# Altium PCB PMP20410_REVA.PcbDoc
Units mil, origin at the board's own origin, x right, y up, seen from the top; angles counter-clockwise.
Board outline 2100 x 1400 mil, 4 copper layers (Top Layer, Signal Layer 1, Signal Layer 2, Bottom Layer), stack 68.2 mil thick; 65 components, 35 nets, 168 pads, 100 vias.
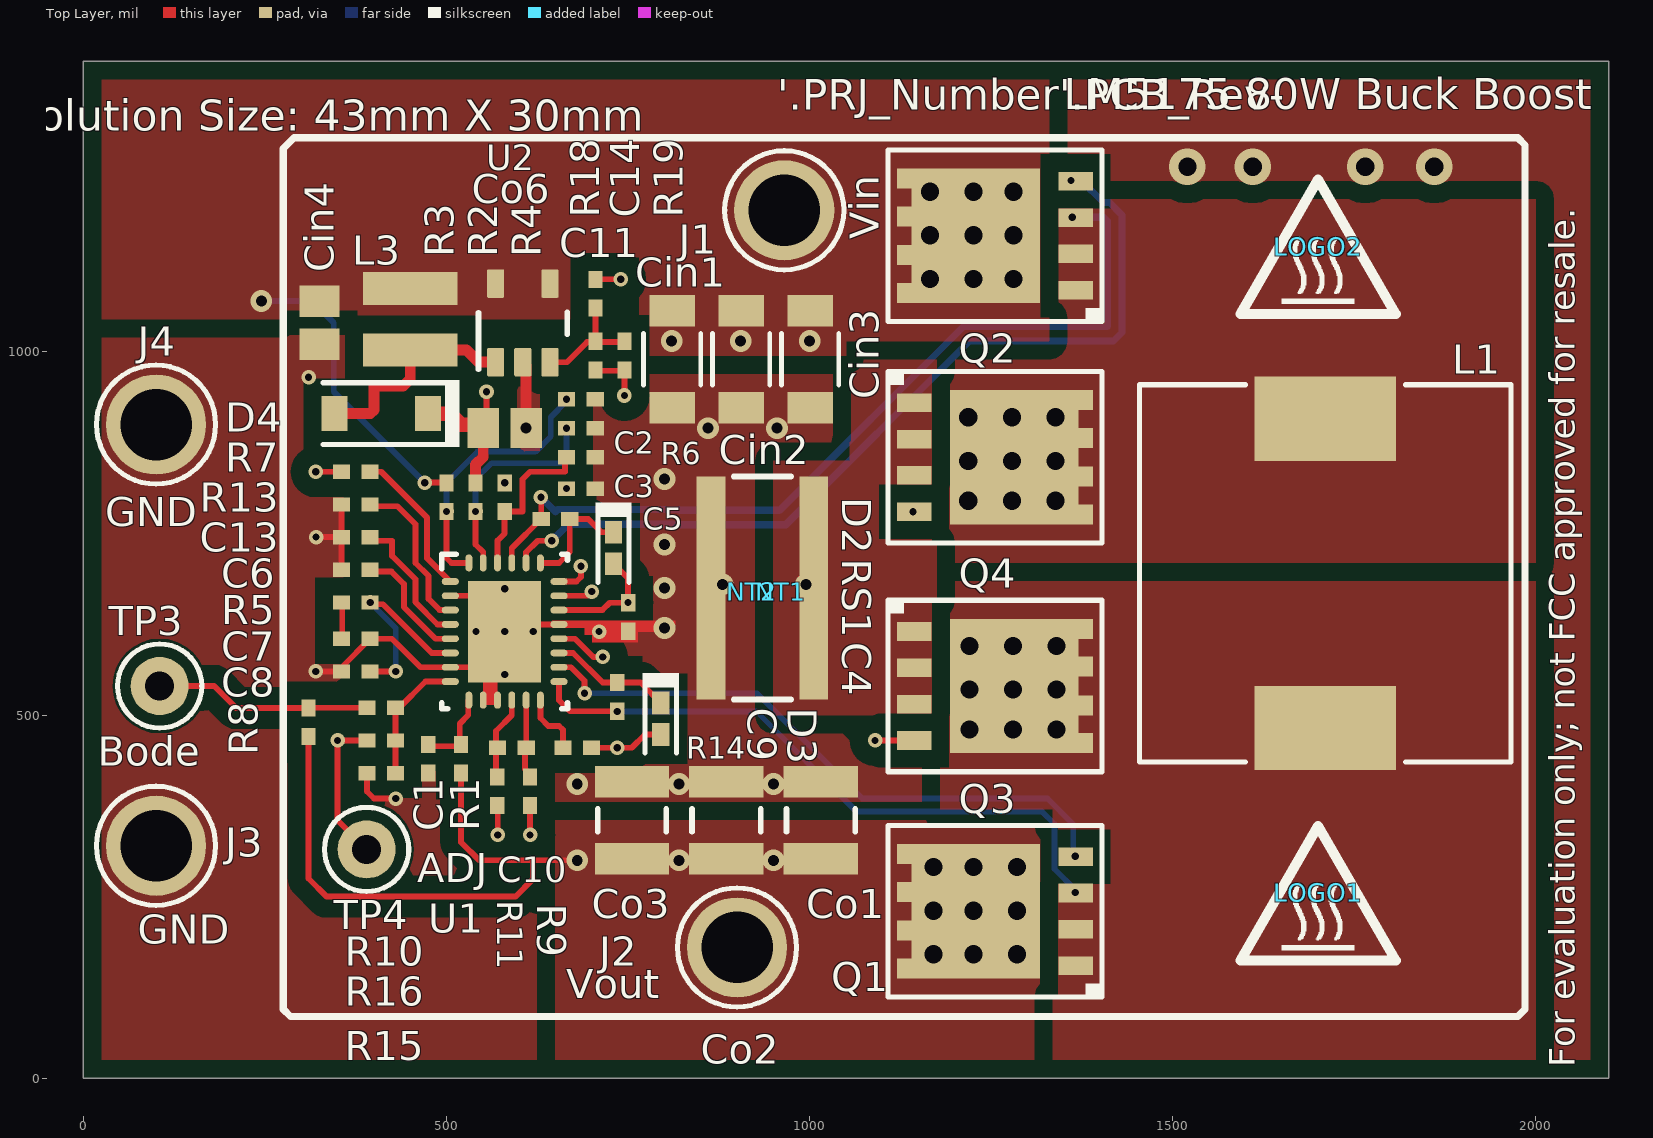
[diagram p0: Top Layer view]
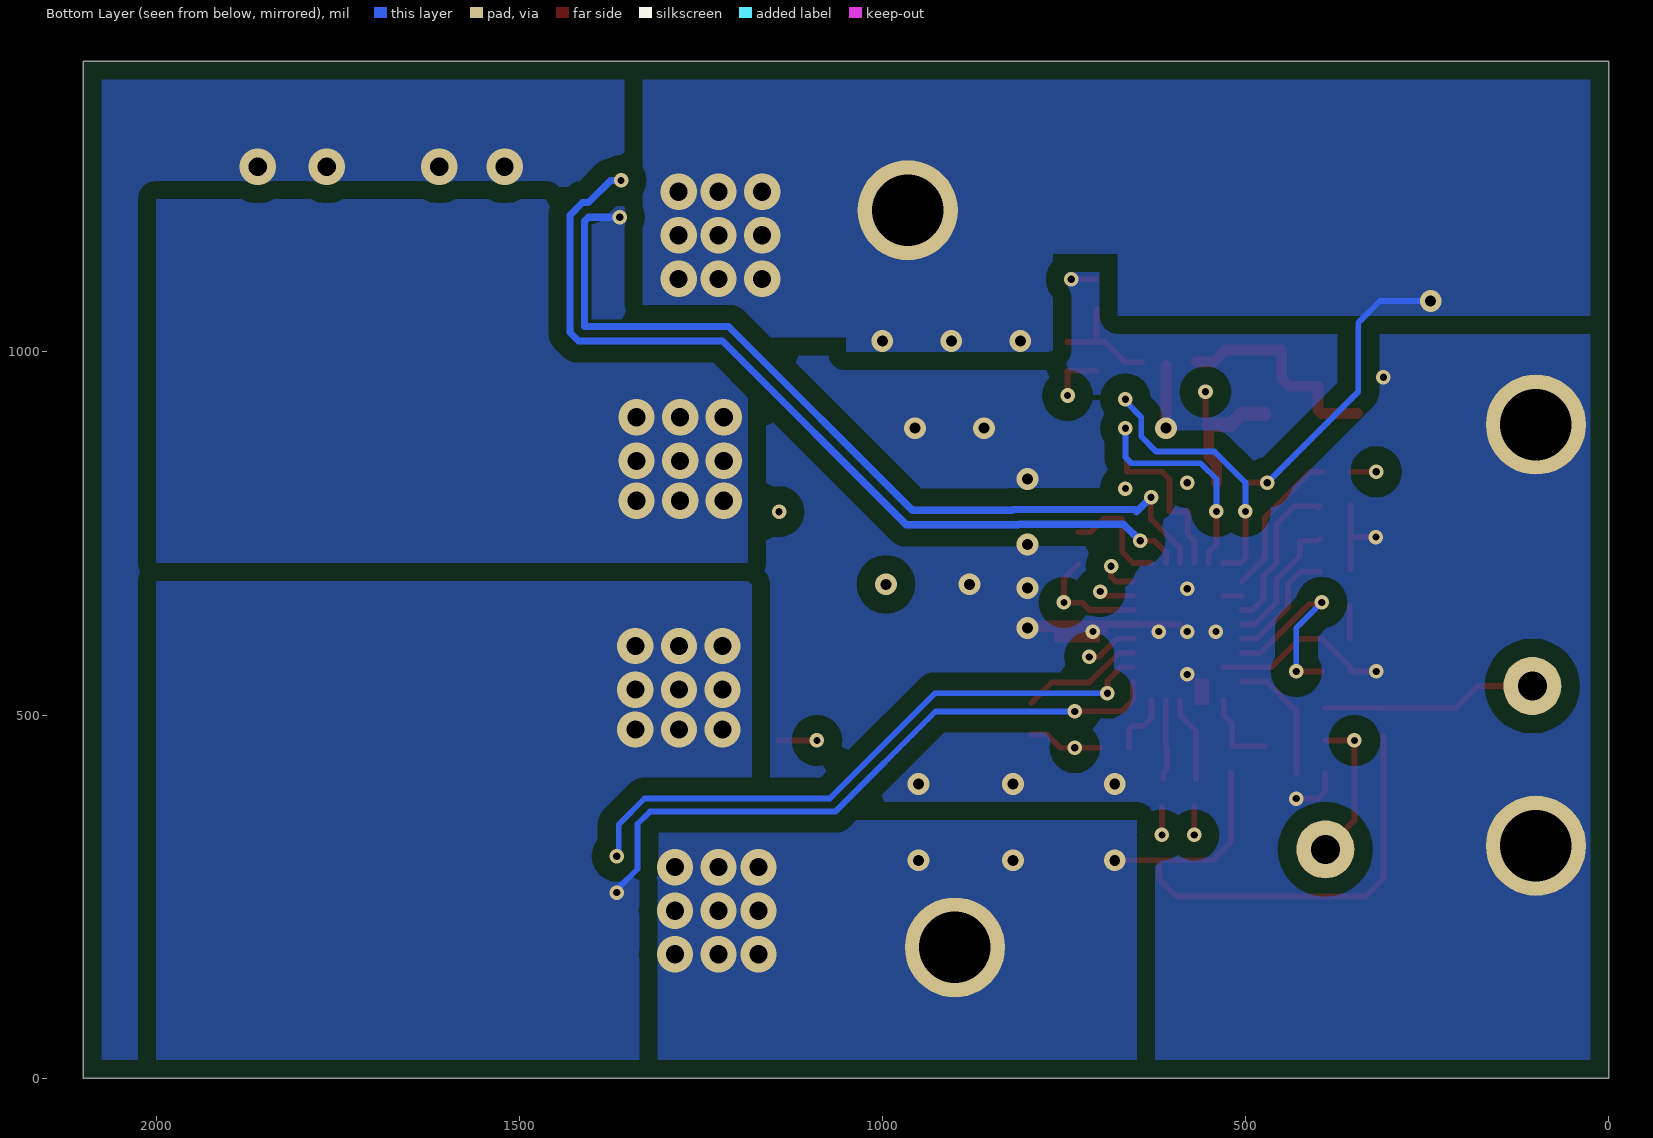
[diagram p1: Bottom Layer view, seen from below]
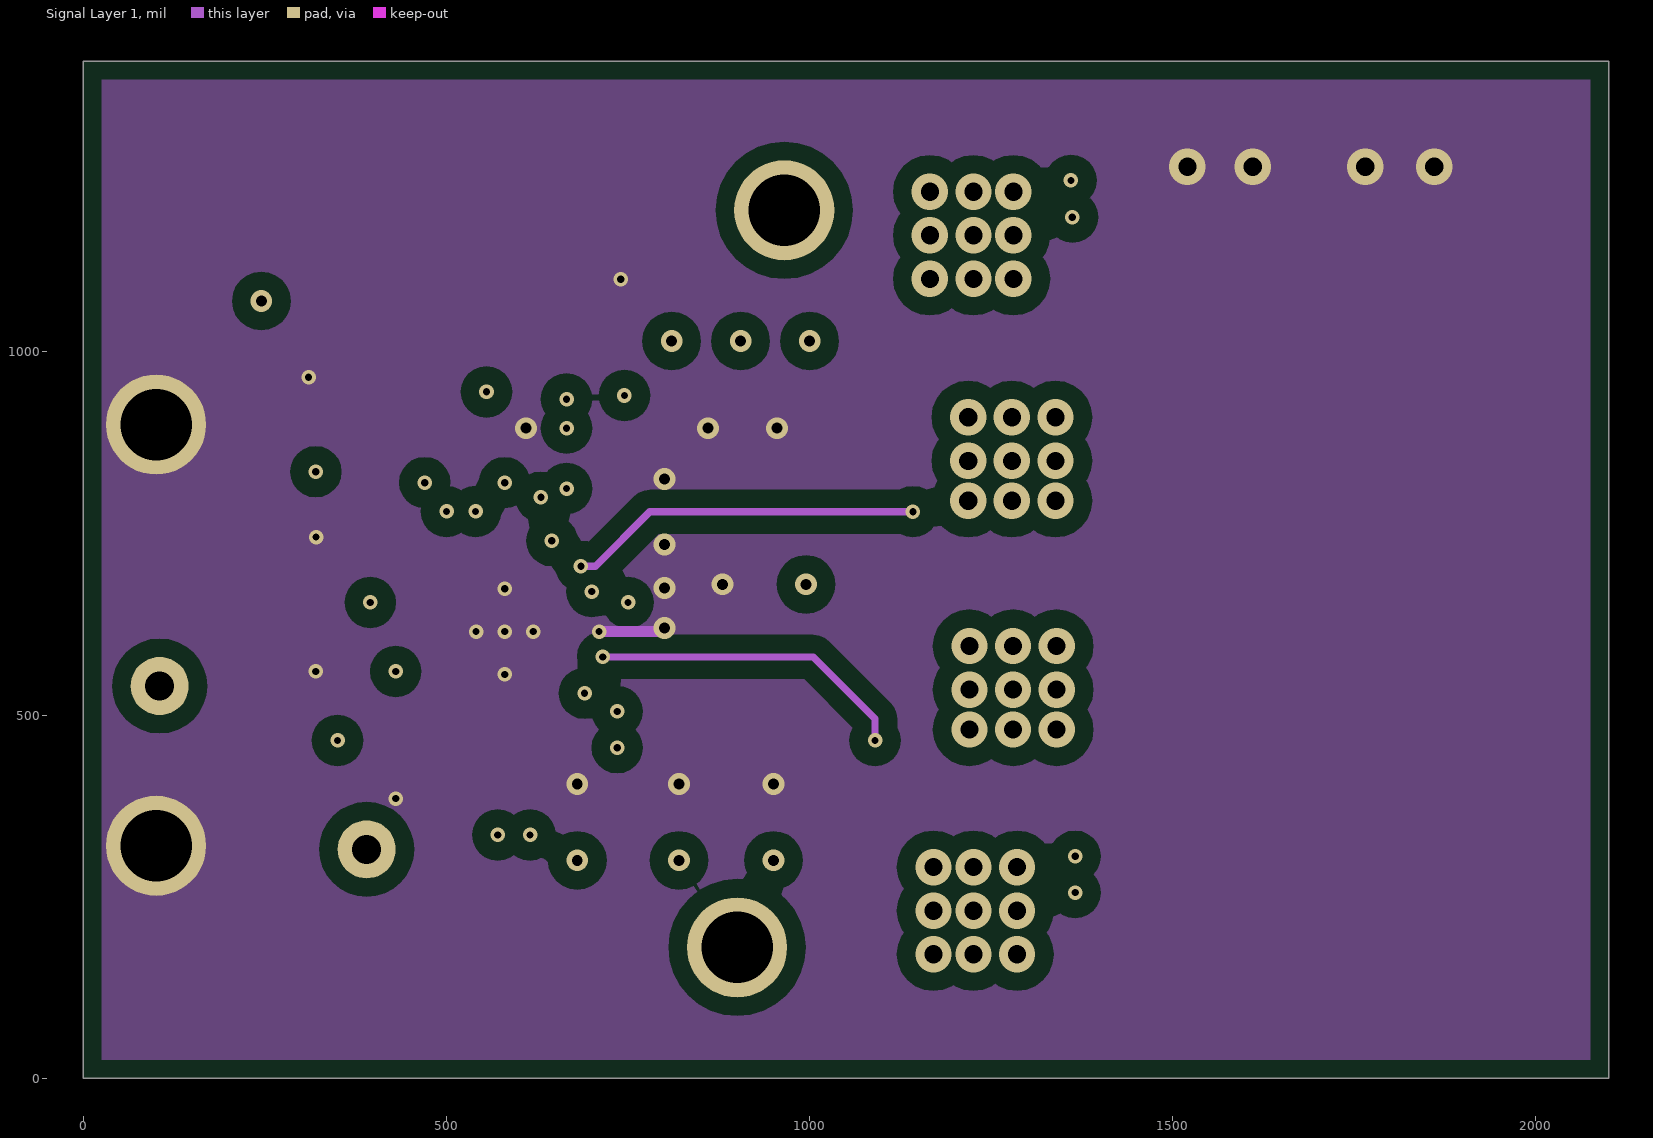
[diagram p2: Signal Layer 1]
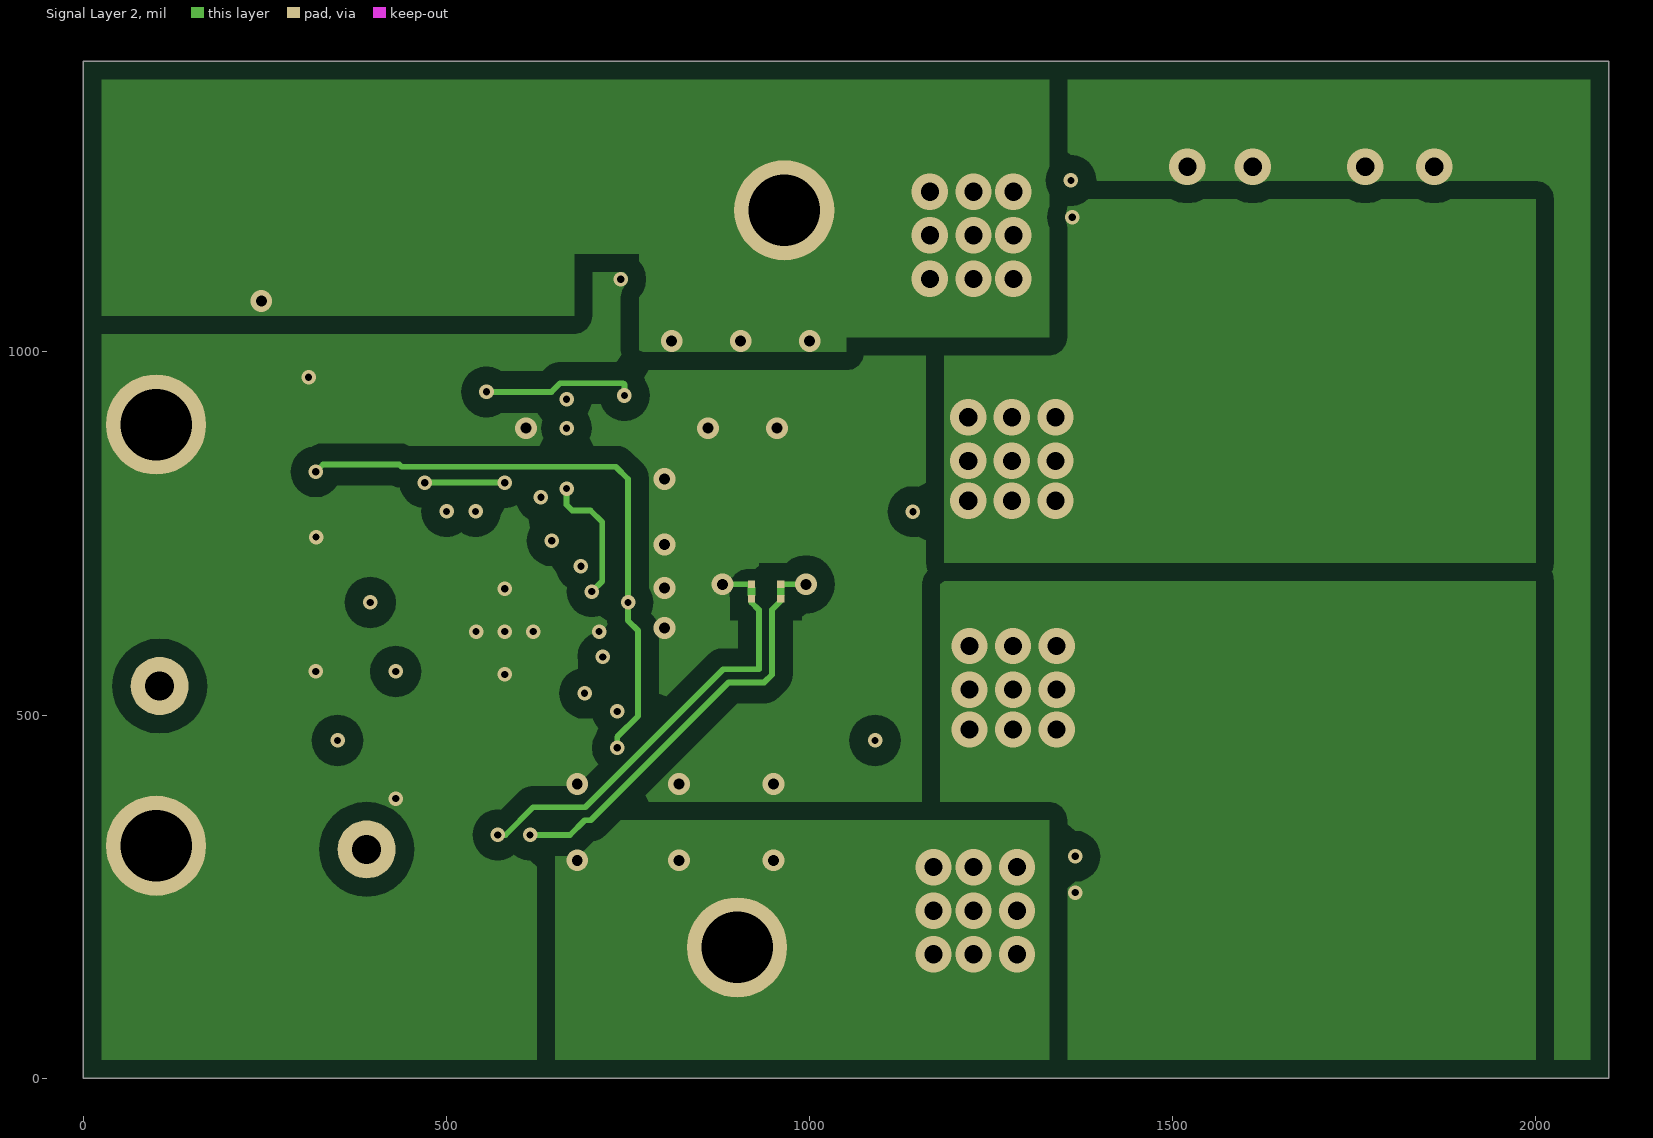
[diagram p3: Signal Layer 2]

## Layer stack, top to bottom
Top Solder: solder mask 0.4, Solder Resist, Dk 3.5
Top Layer: signal copper 2.8
Dielectric1: core 20, FR-4, Dk 4.8
Signal Layer 1: signal copper 2.8
Dielectric 3: prepreg 17, Dk 4.2
Signal Layer 2: signal copper 2.8
Dielectric 2: core 20, Dk 4.2
Bottom Layer: signal copper 2.8
Bottom Solder: solder mask 0.4, Solder Resist, Dk 3.5

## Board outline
0,0 2100,0 2100,1400 0,1400

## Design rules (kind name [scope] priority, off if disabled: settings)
AcuteAngle [All] p1: minimum=4.50000000000000E+0001 checktracksonly=FALSE
AssemblyTestPointUsage [All] p1: valid=2
BoardOutlineClearance BoardOutlineClearance_MountingHoles [OnCopper and InComponentClass('Mounting Holes')] p1: gap=40
BoardOutlineClearance BoardOutlineClearance_Poly [OnCopper and IsPoly] p2: gap=25
BoardOutlineClearance [OnCopper and Not InComponentClass('Logo') and not InComponentClass('FiducialMark') and not InRegion(1000,500,4000,800) and not InPoly] p3: gap=75
Clearance Clearance_Keepouts [((IsTrack Or IsArc) And Not InPoly) And IsFree and IsKeepOut vs ((IsTrack Or IsArc) And Not InPoly) And IsFree and IsKeepOut] p1: gap=0
Clearance Clearance_Poly [InPolygon] p2: gap=25
Clearance [All] p3: gap=7.87
ComponentClearance ComponentClearance_MountingHoles_FiducialMarks [InComponentClass('Mounting Holes') vs InComponentClass('FiducialMark')] p1: gap=50 collisioncheckmode=3 verticalgap=10 showdistances=FALSE
ComponentClearance ComponentClearance_Shunt [InComponentClass('Header') vs InComponentClass('Shunt')] p2: gap=0 collisioncheckmode=3 verticalgap=0 showdistances=FALSE
ComponentClearance ComponentClearance_Logo [InComponentClass('Logo')] p3: gap=50 collisioncheckmode=3 verticalgap=10 showdistances=FALSE
ComponentClearance ComponentClearance_ScrewToNut [(HasFootprint('NY PMS 440 0025 PH')) vs (HasFootprint('Keystone_1902C'))] p4: gap=5 collisioncheckmode=3 verticalgap=10 showdistances=FALSE
ComponentClearance ComponentClearance_MountingHoles [InComponentClass('Mounting Holes')] p5: gap=250 collisioncheckmode=3 verticalgap=100000 showdistances=FALSE
ComponentClearance ComponentClearance_SmallPassives [HasFootprint('0201*') or HasFootprint('0402*') or HasFootprint('0508') or HasFootprint('0603*') or HasFootprint('0612') or HasFootprint('0805*') or HasFootprint('0815*') or HasFootprint('0830*') or HasFootprint('1206*') or HasFootprint('1210*') or HasFootprint('1808*') or HasFootprint('1812*') or HasFootprint('1825*') or HasFootprint('2010*') or HasFootprint('2220*') or HasFootprint('2225*') or HasFootprint('2512*') or HasFootprint('2728*') or HasFootprint('3518*') vs HasFootprint('0201*') or HasFootprint('0402*') or HasFootprint('0508') or HasFootprint('0603*') or HasFootprint('0612') or HasFootprint('0805*') or HasFootprint('0815*') or HasFootprint('0830*') or HasFootprint('1206*') or HasFootprint('1210*') or HasFootprint('1808*') or HasFootprint('1812*') or HasFootprint('1825*') or HasFootprint('2010*') or HasFootprint('2220*') or HasFootprint('2225*') or HasFootprint('2512*') or HasFootprint('2728*') or HasFootprint('3518*')] p6: gap=14.96 collisioncheckmode=3 verticalgap=10 showdistances=FALSE
ComponentClearance ComponentClearance_THtoSMT [IsThruComponent vs IsSMTComponent] p7: gap=40 collisioncheckmode=3 verticalgap=30 showdistances=FALSE
ComponentClearance ComponentClearance_THtoTH [IsThruComponent vs IsThruComponent] p8: gap=30 collisioncheckmode=3 verticalgap=30 showdistances=FALSE
ComponentClearance [All] p9: gap=30 collisioncheckmode=3 verticalgap=10 showdistances=FALSE
DiffPairsRouting [All] p1: maxlimit=100 minlimit=10 mostfreqgap=10 toplayer_minwidth=8 toplayer_maxwidth=15 toplayer_prefwidth=15 midlayer1_minwidth=8 midlayer1_maxwidth=15 midlayer1_prefwidth=15 midlayer2_minwidth=8 midlayer2_maxwidth=15 midlayer2_prefwidth=15 bottomlayer_minwidth=8 bottomlayer_maxwidth=15 bottomlayer_prefwidth=15 maxuncoupledlength=1000
FabricationTestPointUsage TestPointUsage [All] p1: valid=2 allowmultiple=FALSE
FabricationTestpoint Testpoint [All] p1: side=3 testpointundercomponent=TRUE minsize=40 maxsize=100 preferedsize=60 minholesize=0 maxholesize=40 preferedholesize=32 testpointgrid=1 allowsidetop=TRUE allowsidebottom=TRUE usegrid=TRUE gridtolerance=0.01
FanoutControl Fanout_LCC [IsLCC] p1: bgadir=Out bgaviamode=Centered fanoutstyle=Auto fanoutdirection=Alternating viagrid=1 // Fanout_LCC (Default Rule)
FanoutControl Fanout_BGA [IsBGA] p2: bgadir=Out bgaviamode=Centered fanoutstyle=Auto fanoutdirection=Alternating viagrid=1 // Fanout_BGA (Default Rule)
FanoutControl Fanout_Default [All] p4: bgadir=Out bgaviamode=Centered fanoutstyle=Auto fanoutdirection=Alternating viagrid=1 // Fanout_Default (Default Rule)
FanoutControl Fanout_Small [(CompPinCount < 5)] p5: bgadir=Out bgaviamode=Centered fanoutstyle=Auto fanoutdirection=OutThenIn viagrid=1 // Fanout_Small (Default Rule)
HoleSize [All] p1: absolutevalues=TRUE maxlimit=251 minlimit=7.87 maxpercent=80.000 minpercent=20.000
MinimumAnnularRing MinimumAnnularRing_ThermalPadVias [IsVia and InAnyComponent] p1: minimumring=5
MinimumAnnularRing [All] p2: minimumring=5
MinimumSolderMaskSliver MinimumSolderMaskSliver_Logo [InComponentClass('Logo') vs InComponentClass('Logo')] p1: minsoldermaskwidth=0.7
MinimumSolderMaskSliver [All] p2: minsoldermaskwidth=3.94
PlaneConnect [All] p1: planeconnectstyle=Direct reliefexpansion=10 reliefentries=4 reliefconductorwidth=10 reliefairgap=10
PolygonConnect [All] p1: connectstyle=Direct reliefconductorwidth=10 reliefentries=4 polygonreliefangle="90 Angle" airgapwidth=10
RoutingVias ThermalPadVias [IsVia and InAnyComponent] p1: holewidth=7.87 width=19.68 viastyle="Through Hole" minholewidth=5 minwidth=19.68 maxholewidth=12.99 maxwidth=23.62
RoutingVias [All] p2: holewidth=16 width=34 viastyle="Through Hole" minholewidth=5 minwidth=20 maxholewidth=40 maxwidth=65
SilkToBoardRegionClearance [Not ((IsComment or IsDesignator) And (Hide <> 'False')) and not InRegion(1000,500,4000,800)] p1:
SilkToSilkClearance SilkToSilkClearance_Pb-FreeLogo [(HasFootprint('Pb-Free_Overlay_Medium') OR HasFootprint('Pb-Free_Overlay_Small')) vs (HasFootprint('Pb-Free_Overlay_Medium') OR HasFootprint('Pb-Free_Overlay_Small'))] p1: silktosilkclearance=0
SilkToSilkClearance [All] p2: silktosilkclearance=4
SilkToSolderMaskClearance SilkToComponentPadClearance [IsPad and InAnycomponent] p1: minsilkscreentomaskgap=5 clearancetoexposedcopper=TRUE
SilkToSolderMaskClearance "Silk to Solder Mask Opening" [All] p2: minsilkscreentomaskgap=4 clearancetoexposedcopper=FALSE
SolderMaskExpansion [All] p1: expansion=1.97
Width [All] p1: maxlimit=100 minlimit=6 preferedwidth=10 checkconnectedcopper=TRUE
15 further rules are at their usual default settings.

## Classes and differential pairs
component class PMP20410_REVA: C1 C2 C3 C4 C5 C6 C7 C8 C9 C10 C11 C13 C14 Cin1 Cin2 Cin3 Cin4 Co1 Co2 Co3 Co6 D2 D3 D4 J1 J2 J3 J4 L1 L3 NT1 NT2 Q1 Q2 Q3 Q4 R1 R2 R3 R4 R5 R6 R7 R8 R9 R10 R11 R13 R14 R15 R16 R18 R19 RS1 TP3 TP4 U1 U2
component class AssemblyNote: ZZ1 ZZ2 ZZ3 ZZ4
component class PMP20410_REVA_Hardware: LOGO1 LOGO2 Logo3 ZZ1 ZZ2 ZZ3 ZZ4
differential pair HDRV2: +HDRV2_P -HDRV2_N
differential pair HDRV1: +HDRV1_P -HDRV1_N
differential pair CS: +CS_P -CS_N

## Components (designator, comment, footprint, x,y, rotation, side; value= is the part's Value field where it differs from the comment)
C1 "CC0402KRX7R9BB101" 0402L 475,440 r270 top
C2 "GCM155R71H104KE02D" 0402L 685,895 r0 top
C3 "C1005X5R1E224M050BC" 0402L 685,811.79 r0 top
C4 "C1005X5R1C105K050BC" 0402L 750,635 r270 top
C5 "GCM155R71H104KE02D" 0402L 650,770 r180 top
C6 "C1005X5R1E224M050BC" 0402L 375,700 r180 top
C7 "GRM155R71E473KA88D" 0402L 375,605 r0 top
C8 "GRM155R71E223KA61D" 0402L 375,560 r180 top
C9 "GCM155R71H104KE02D" 0402L 735,525 r90 top
C10 "C1005X7R1H221K" 0402L 590,455 r180 top
C11 "CC0402KRX7R9BB101" 0402L 685,935 r180 top
C13 "GRM1555C1H680JA01D" 0402L 375,745 r180 top
C14 "GRM155R71H561KA01D" 0402L 745,995 r90 top
Cin1 "GRM31CR71A226ME15L" 1206_180 810.63,990 r270 top
Cin2 "GRM31CR71A226ME15L" 1206_180 905.63,990 r270 top
Cin3 "GRM31CR71A226ME15L" 1206_180 1000.63,990 r270 top
Cin4 "GRM21BR71C475KA73L" 0805L 325,1040 r270 top
Co1 "GRM32ER71E226KE15L" 1210_270L 1015.32,355 r90 top
Co2 "GRM32ER71E226KE15L" 1210_270L 885.32,355 r90 top
Co3 "GRM32ER71E226KE15L" 1210_270L 755.32,355 r90 top
Co6 "GRM21BR71C475KA73L" 0805L 580,895 r0 top
D2 "BAS516,115" SOD-523 730,730 r270 top
D3 "BAS516,115" SOD-523 795,495 r270 top
D4 "MBR0520LT1G" SOD-123 410,915 r180 top
J1 "Vin" Keystone1598-2 965,1195 r0 top
J2 "Vout" Keystone1598-2 900,180 r0 top
J3 "GND" Keystone1598-2 100,320 r0 top
J4 "GND" Keystone1598-2 100,900 r0 top
L1 "IHLP5050FDERR68M01" IHLP-5050FD 1710,695 r270 top
L3 "LQH3NPN100NG0" LQH3NP_G0 450,1045 r270 top
LOGO1 "CAUTION HOT SURFACE" IEC_HotSurface_Small 1700,255 r0 top
LOGO2 "CAUTION HOT SURFACE" IEC_HotSurface_Small 1700,1145 r0 top
Logo3 "FCC disclaimer" FCC_disclaimer 2350,3380 r0 top
NT1 "Net-Tie" Net-Tie_10mil 960,670 r270 top net-tie
NT2 "Net-Tie" Net-Tie_10mil 920,670 r270 top net-tie
Q1 "BSC014NE2LSI" PG-TDSON-8 1255,230 r180 top
Q2 "BSC014NE2LSI" PG-TDSON-8 1255,1160 r180 top
Q3 "BSC014NE2LSI" PG-TDSON-8 1255,540 r0 top
Q4 "BSC014NE2LSI" PG-TDSON-8 1255,855 r0 top
R1 "CRCW040210R0JNED" 0402L 520,440 r270 top
R2 "CRCW040210R0JNED" 0402L 540,800 r90 top
R3 "CRCW040210R0JNED" 0402L 500,800 r270 top
R4 "CRCW040271K5FKED" 0402L 580,800 r90 top
R5 "CRCW04021K50FKED" 0402L 375,655 r0 top
R6 "CRCW040261K9FKED" 0402L 685,855 r180 top
R7 "CRCW04020000Z0ED" 0402L 375,835 r180 top
R8 "CRCW040247R0JNED" 0402L 310,490 r90 top
R9 "CRCW0402100RFKED" 0402L 615,395 r270 top
R10 "CRCW040249K9FKED" 0402L 410,510 r180 top
R11 "CRCW0402100RFKED" 0402L 570,395 r270 top
R13 "CRCW0402130KFKED" 0402L 375,790 r0 top
R14 "CRCW040220K0JNED" 0402L 680,455 r0 top
R15 "CRCW04025K49FKED" 0402L 410,420 r0 top
R16 "CRCW040216K2FKED" 0402L 410,465 r0 top
R18 "CRCW040249K9FKED" 0402L 705,995 r270 top
R19 "CRCW04026K98FKED" 0402L 705,1080 r270 top
RS1 "FCSL76R002GER" FSCL76 935,675 r0 top
TP3 "Bode" Keystone5002 105,540 r0 top
TP4 "ADJ" Keystone5002 390,315 r0 top
U1 "LM5175RHFR" RHF0028A 580,615 r0 top
U2 "LMR62014XMF/NOPB" DBV0005A_N 605,1040 r90 top
ZZ1 "This Assembly Note is for PCB labels only" AssemblyNoteLabel 185,3938 r0 top
ZZ2 "These assemblies are ESD sensitive, ESD precautions shall be observed." AssemblyNote 185,3829.11 r0 top
ZZ3 "These assemblies must be clean and free from flux and all contaminants. Use of no clean flux is not acceptable." AssemblyNote 185,3740.56 r0 top
ZZ4 "These assemblies must comply with workmanship standards IPC-A-610 Class 2, unless otherwise specified." AssemblyNote 185,3652 r0 top

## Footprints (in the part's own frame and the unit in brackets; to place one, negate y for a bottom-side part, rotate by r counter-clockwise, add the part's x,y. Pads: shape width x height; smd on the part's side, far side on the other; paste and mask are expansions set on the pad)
0402L [mm] "0402 from SM-752 data"
  rect 0.6x0.5 smd: 1(-0.5,0) 2(0.5,0)
  body extent -0.55,-0.3 0.55,0.3, height 0.6
0805L [mm] "0805 from SM-752 data"
  rect 1.1x1.4 smd: 1(-0.75,0) 2(0.75,0)
  body extent -1.1,-0.72 1.1,0.72, height 1.45
1206_180 [mm] "1206_180"
  rect 1.1x1.6 smd: 1(-1.7,0) 2(1.7,0)
  silkscreen extent -0.9,-1 0.9,1, body extent -1.75,-0.95 1.75,0.95, height 1.8
1210_270L [mm] "1210"
  rect 1.1x2.6 smd: 1(-1.35,0) 2(1.35,0)
  silkscreen extent -0.4,-1.2 0.4,1.2, body extent -1.7,-1.35 1.7,1.35, height 2.7
AssemblyNote [mil] "Assembly Note"
AssemblyNoteLabel [mil] "Assembly Note for PCB Labels"
DBV0005A_N [mm] "SOT23, 5-Leads, Body 2.9x1.6mm, Pitch 0.95mm, Lead Span 2.8mm, IPC Medium Density"
  rrect17% 1x0.6 smd: 1(-1.375,0.95) 2(-1.375,0) 3(-1.375,-0.95) 4(1.375,-0.95) 5(1.375,0.95)
  silkscreen extent -1.63,-1.55 0.38,1.55, body extent -1.42,-1.46 1.42,1.46, height 1.09
FCC_disclaimer [mil]
FSCL76 [mm] "OHMITE"
  rect 1x7.8 smd: 1(-1.8,0) 2(1.8,0)
  silkscreen extent -1,-3.9 1,3.9, body extent -1.9,-3.8 1.9,3.8, height 0.7
IEC_HotSurface_Small [mil]
  silkscreen extent -107,-93 107,92
IHLP-5050FD [mm] "Vishay Dale recommended land pattern.  Document 34123 rev 18-Sep-09"
  rect 2.945x4.95 smd: 1(-5.407,0) 2(5.407,0)
  silkscreen extent -6.6,-6.5 6.6,6.5, body extent -6.86,-6.45 6.86,6.45, height 6.5
Keystone1598-2 [mm] "Triple Turret"
  round 3.5 hole 2.5: 1(0,0)
  silkscreen extent -2.08,-2.08 2.08,2.08, body extent -1.6,-1.6 1.59,1.6, height 7.72
Keystone5002 [mil] "For Keystone 500x miniature loop terminals"
  round 80 hole 40: 1(0,0)
  silkscreen extent -58,-58 58,58, body extent -49,-49 49,49, height 182
LQH3NP_G0 [mm] "MURATA"
  rect 1.15x3.3 smd: 1(-1.075,0) 2(1.075,0)
  body extent -1.6,-1.6 1.6,1.6, height 1.01
Net-Tie_10mil [mil] "10mil net tie, no solder mask opening, no solder paste"
  rect 10x10 on Mid2 paste-5 mask-5: 1(-10,0) 2(10,0)
  Signal Layer 2 region: -6,5 6,5 6,-5 -6,-5
PG-TDSON-8 [mm] "Infineon recommended land pattern"
  rect 1.2x0.65 smd: 1(-2.825,1.905) 2(-2.825,0.635) 3(-2.825,-0.635) 4(-2.825,-1.905)
  rect 0.5x0.7 smd: 5(3.175,-2) 6(3.175,-0.675) 7(3.175,0.675) 8(3.175,2)
  rect 4.5x4.7 smd paste-2.25: 9(0.675,0)
  silkscreen extent -3.74,-3 3.74,3, body extent -3.18,-2.89 3.18,2.9, height 1.1
RHF0028A [mm] "QFN, 28-Leads, Body 5x4mm, Pitch 0.5mm, Thermal Pad 3.55x2.55mm"
  oval 0.6x0.24 smd: 1(-1.9,1.75) 2(-1.9,1.25) 3(-1.9,0.75) 4(-1.9,0.25) 5(-1.9,-0.25) 6(-1.9,-0.75) 7(-1.9,-1.25) 8(-1.9,-1.75) 15(1.9,-1.75) 16(1.9,-1.25) 17(1.9,-0.75) 18(1.9,-0.25) 19(1.9,0.25) 20(1.9,0.75) 21(1.9,1.25) 22(1.9,1.75)
  oval 0.24x0.6 smd: 9(-1.25,-2.4) 10(-0.75,-2.4) 11(-0.25,-2.4) 12(0.25,-2.4) 13(0.75,-2.4) 14(1.25,-2.4) 23(1.25,2.4) 24(0.75,2.4) 25(0.25,2.4) 26(-0.25,2.4) 27(-0.75,2.4) 28(-1.25,2.4)
  rect 2.55x3.55 smd paste-3.55: 29(0,0)
  silkscreen extent -2.2,-2.7 2.2,2.7, body extent -2.07,-2.57 2.07,2.57, height 1.01
SOD-123 [mm] "On Semi recommended land pattern"
  rect 0.915x1.22 smd: 1(-1.637,0) 2(1.637,0)
  silkscreen extent -2.74,-1.17 2.03,1.17, body extent -1.93,-0.9 1.93,0.9, height 1.35
SOD-523 [mm] "NXP Semiconductor recommended land pattern, nominal STEP model"
  rect 0.8x0.6 smd paste-0.05: 1(-0.55,0) 2(0.55,0)
  silkscreen extent -1.6,-0.64 1.2,0.63, body extent -0.8,-0.4 0.8,0.4, height 0.72

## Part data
C1 C11: "CAP, CERM, 100 pF, 50 V, +/- 10%, X7R, 0402"
C2 C5 C9: "CAP, CERM, 0.1 µF, 50 V, +/- 10%, X7R, AEC-Q200 Grade 1, 0402"
C3 C6: "CAP, CERM, 0.22 µF, 25 V, +/- 20%, X5R, 0402"
C4: "CAP, CERM, 1 µF, 16 V, +/- 10%, X5R, 0402"
C7: "CAP, CERM, 0.047 µF, 25 V, +/- 10%, X7R, 0402"
C8: "CAP, CERM, 0.022 µF, 25 V, +/- 10%, X7R, 0402"
C10: "CAP, CERM, 220 pF, 50 V, +/- 10%, X7R, 0402"
C13: "CAP, CERM, 68 pF, 50 V, +/- 5%, C0G/NP0, 0402"
C14: "CAP, CERM, 560 pF, 50 V, +/- 10%, X7R, 0402"
Cin1 Cin2 Cin3: "CAP, CERM, 22 µF, 10 V, +/- 20%, X7R, 1206"
Cin4 Co6: "CAP, CERM, 4.7 µF, 16 V, +/- 10%, X7R, 0805"
Co1 Co2 Co3: "CAP, CERM, 22 µF, 25 V, +/- 10%, X7R, 1210"
D2 D3: "Diode, Switching, 100V, 0.25A, SOD-523"
D4: "Diode, Schottky, 20 V, 0.5 A, SOD-123"
J1 J2 J3 J4: library part 1598-2, "Terminal, Turret, TH, Triple"
L1: "Inductor, Shielded, Powdered Iron, 680 nH, 35 A, 0.0016 ohm, SMD"
L3: "Inductor, Wirewound, Ferrite, 10 µH, 0.5 A, 0.57 ohm, SMD"
LOGO1 LOGO2: library part IEC_HotSurface, "IEC 61010-1 Hot Surface Warning"
Logo3: library part FCC_disclaimer, "FCC_disclaimer"
NT1 NT2: "Single point connection between nets."
Q1 Q2 Q3 Q4: "MOSFET, N-CH, 25 V, 33 A, PG-TDSON-8"
R1 R2 R3: "RES, 10, 5%, 0.063 W, 0402"
R4: "RES, 71.5 k, 1%, 0.063 W, 0402"
R5: "RES, 1.50 k, 1%, 0.063 W, 0402"
R6: "RES, 61.9 k, 1%, 0.063 W, 0402"
R7: "RES, 0, 5%, 0.063 W, 0402"
R8: "RES, 47, 5%, 0.063 W, 0402"
R9 R11: "RES, 100, 1%, 0.063 W, 0402"
R10 R18: "RES, 49.9 k, 1%, 0.063 W, 0402"
R13: "RES, 130 k, 1%, 0.063 W, 0402"
R14: "RES, 20 k, 5%, 0.063 W, 0402"
R15: "RES, 5.49 k, 1%, 0.063 W, 0402"
R16: "RES, 16.2 k, 1%, 0.063 W, 0402"
R19: "RES, 6.98 k, 1%, 0.063 W, 0402"
RS1: "RES, 0.002, 2%, 3 W, 2.8x7.6x.7mm"
TP3 TP4: library part 5002, "Test Point, Miniature, White, TH"
U1: "42-V Wide VIN Synchronous 4-Switch Buck-Boost Controller, RHF0028A"
U2: "LMR62014 SIMPLE SWITCHER® 20Vout, 1.4 A Step-Up Voltage Regulator, DBV0005A"
ZZ1: library part AssemblyNoteLabel
ZZ2 ZZ3 ZZ4: library part AssemblyNote

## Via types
v1: diameter 20, hole 10, Top Layer to Bottom Layer, 41 vias
v2: diameter 50, hole 25, Top Layer to Bottom Layer, 40 vias
v3: diameter 30, hole 15, Top Layer to Bottom Layer, 19 vias

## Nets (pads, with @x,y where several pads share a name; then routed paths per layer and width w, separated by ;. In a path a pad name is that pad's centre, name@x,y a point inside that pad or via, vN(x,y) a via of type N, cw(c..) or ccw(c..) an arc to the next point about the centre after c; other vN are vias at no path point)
10V: C14.1 Co6.1 D4.1 R2.2 R18.2 | length 503.6
  Top Layer w8: Co6.1 555,899.53 v1(555,945) ; R18.2@705,974.11 745,974.11 v1(745,940)
  Top Layer w15: R2.2 540,845 550.47,855.47 Co6.1 Co6.1@550.47,900
  Top Layer w20: D4.1 505,915 520,900 Co6.1@550.47,900
  Signal Layer 2 w8: v1(555,945) 644.38,945 656.25,956.87 743.13,956.87 745,955 v1(745,940)
ADJ: R16.1 TP4.1 | length 206.9
  Top Layer w8: TP4.1 350,355 v1(350,465) R16.1
BIAS: C3.1 U1.21 | length 230.7
  Top Layer w8: U1.21 694.21,664.21 v1(700,670) ; C3.1@665,811.48 v1(665.32,811.79)
  Signal Layer 2 w8: v1(665.32,811.79) 665.32,789.68 673.19,781.81 698.19,781.81 714.31,765.69 714.31,684.31 v1(700,670)
BOOT1: C5.1 D2.1 U1.23 | length 160.2
  Top Layer w8: U1.23 654.8,709.49 669.68,724.37 C5.1 695,770 713.35,751.65 D2.1
BOOT2: C9.2 D3.1 U1.17 | length 168.7
  Top Layer w8: U1.17 674.21,585.47 715,544.69 C9.2 766.97,544.69 D3.1
COMP: C8.1 R5.2 U1.6 | length 280.3
  Top Layer w8: C8.1 v1(430,560) ; R5.2@397.48,652.46 412.54,652.46 479.53,585.47 U1.6
  Bottom Layer w8: v1(395,655) 430,620 v1(430,560)
CS_N: NT2.2 R11.2 | length 594.8
  Top Layer w8: v1(570.53,335) R11.2@570.53,374.79
  Signal Layer 2 w8: v1(570.53,335) 581.06,335 619.18,373.13 691.13,373.13 881.01,563 930,563 930,645 920,655 NT2.2
CS_P: NT1.2 R9.2 | length 572.1
  Top Layer w8: v1(615,335) R9.2@615,373.37
  Signal Layer 2 w8: v1(615,335) 670,335 690.13,355.13 698.59,355.13 888.46,545 937.46,545 948,555.54 948,645 960,657 NT1.2
EN: R4.1 R6.2 U1.26 | length 227.6
  Top Layer w8: U1.26 570.16,740.16 580,750 R4.1 604.68,780.32 604.68,824.68 615,835 663.19,835 663.19,852.87 R6.2
FB: R10.1 R15.2 R16.2 U1.8 | length 176.2
  Top Layer w8: R15.2 R16.2 429.69,507.37 R10.1@432.32,510 ; R10.1@435,510 471.1,546.1 U1.8
GND: C1.2 C2.2 C3.2 C4.2 C6.2 C7.2 C8.2 C11.1 C13.2 Cin1.2 Cin2.2 Cin3.2 Cin4.2 Co1.2 Co2.2 Co3.2 Co6.2 J3.1 J4.1 NT2.1 R6.1 R13.1 R15.1 R19.1 RS1.1 U1.2 U1.7 U1.10 U1.11 U1.19 U1.29 U2.2 | length 772.7
  Top Layer w8: v1(320,560) C8.2 ; v1(320.31,745) C13.2 ; C8.2@355.31,565.63 C7.2 ; C6.2 R13.1 ; R15.1 390.32,394.68 400,385 v1(430,385) ; C7.2@395.89,605 425,605 464.21,565.79 U1.7 U1.29@530.79,565.79 ; U1.2 U1.29@530.79,664.21 ; U1.29@589.84,624.84 U1.19 ; R19.1@705.32,1100 v1(740,1100)
  Top Layer w15: v3(609.53,895) U2.2@609.53,981.34
  Signal Layer 1 w15: v1(710,615) v3@795,615
  Signal Layer 2 w8: v3(880,680) NT2.1
  other v1: 580,555.94 540.63,615 580,615 619.37,615 580,674.06 310,965
  other v2: 1520,1255 1610,1255 1765,1255 1860,1255
  other v3: 680,405 820,405 950,405 800,620 800,675 800,735 800,825 860,895 955,895
HDRV1_N: C5.2 L1.1 Q2.1 Q2.2 Q2.3 Q4.5 Q4.6 Q4.7 Q4.8 Q4.9 U1.25 | length 1197.7
  Top Layer w8: U1.25 589.84,729.84 C5.2@630,770 ; v1(630,800) 630.31,799.69 C5.2
  Bottom Layer w10: v1(630,800) 650.13,779.87 653.13,782.87 819.83,782.87 820.83,781.87 958.59,781.87 1211.72,1035 1410,1035 1410,1180 1404.41,1185.59 v1(1361.69,1185.59)
  other v2: 1218.43,795 1278.43,795 1338.43,795 1218.43,850 1278.43,850 1338.43,850 1218.43,910 1278.43,910 1338.43,910
HDRV1_P: Q2.4 U1.24 | length 1217.1
  Top Layer w8: U1.24 609.53,724.07 625.46,740 v1(645,740) ; v1(1359.78,1236.08) Q2.4@1360.27,1235.59
  Bottom Layer w8: v1(1359.78,1236.08) v1@1362.28,1238.59
  Bottom Layer w10: v1(645,740) 667.87,762.87 811.55,762.87 812.55,761.87 966.87,761.87 1220,1015 1418.28,1015 1430,1026.72 1430,1188.28 1412.69,1205.59 1404.41,1205.59 1373.92,1236.08 v1(1359.78,1236.08)
HDRV2_N: C9.1 L1.2 Q1.1 Q1.2 Q1.3 Q3.5 Q3.6 Q3.7 Q3.8 Q3.9 U1.15 | length 884.6
  Top Layer w8: U1.15 654.8,520.51 670,505.32 734.68,505.32 v1(735,505)
  Bottom Layer w8: v1(735,505) 926.93,505 1064.93,367 1320,367 1337,350 1337,288 1365.47,259.53 v1(1365.47,255.59)
  other v2: 1220,480 1280,480 1340,480 1220,535 1280,535 1340,535 1220,595 1280,595 1340,595
HDRV2_P: Q1.4 U1.16 | length 847.4
  Top Layer w8: U1.16 671.45,565.79 690,547.24 v1(690,530)
  Bottom Layer w8: v1(690,530) 927.38,530 1072.38,385 1327.46,385 1363,349.46 v1@1363,310
  other v1: 1365.47,305.59
LDRV1: Q4.4 U1.22 | length 536
  Top Layer w8: U1.22 678.9,683.9 685,690 v1(685,705)
  Signal Layer 1 w10: v1(685,705) 705,705 779.87,779.87 1142.08,779.87 v1(1142.2,780)
LDRV2: Q3.4 U1.18 | length 567.8
  Top Layer w8: U1.18@654.96,605 U1.18 676.98,605.16 702.13,580 v1(715,580) v1@718.01,580 ; v1(1090,465) Q3.4
  Signal Layer 1 w10: v1(715,580) 1005,580 1090,495 v1(1090,465)
MODE: R7.1 U1.1 | length 205.8
  Top Layer w8: R7.1 410,835 473.28,771.72 473.28,715.81 U1.1
NetC7_1: C7.1 R5.1 | length 45.9
  Top Layer w8: C7.1@356.52,605 R5.1@356.52,650.86
NetC10_1: C10.1 R9.1 U1.13 | length 108.1
  Top Layer w8: C10.1@607.87,452.46 607.87,425.77 613.19,420.46 R9.1@613.19,412.14 ; U1.13 609.68,520.35 C10.1
NetC10_2: C10.2 R11.1 U1.12 | length 117.3
  Top Layer w8: R11.1@568.19,412.14 568.19,478.19 589.84,499.84 U1.12
NetC14_2: C14.2 R18.1 R19.2 U2.3 | length 159.7
  Top Layer w8: U2.3 665.87,985.87 693.48,1013.48 R18.1@705,1013.48 ; R19.2@705,1059.11 R18.1@705,1013.48 ; C14.2@745,1013.48 R18.1@705,1013.48
NetD4_2: D4.2 L3.2 U2.1 | length 308
  Top Layer w15: D4.2 395,915 400,920 400,952.68 440.18,952.68 450,962.5 L3.2 527.32,1002.68 544.13,985.87 U2.1
NetR8_2: R8.2 R10.2 TP3.1 | length 297.6
  Top Layer w8: TP3.1 180,540 210.31,509.69 R8.2 ; R8.2@310.31,510 R10.2
PGOOD: R14.1 U1.14 | length 87.2
  Top Layer w8: U1.14 629.21,495.79 640,485 655,485 660.32,479.68 R14.1
SLOPE: C13.1 U1.4 | length 187.1
  Top Layer w8: C13.1@397.48,742.46 400.02,739.92 425,739.92 425,719.2 457.1,687.1 457.1,655.45 487.71,624.84 U1.4
SS: C6.1 U1.5 | length 164.5
  Top Layer w8: C6.1@397.48,697.46 424.29,697.46 441.22,680.52 441.22,648.88 484.94,605.16 U1.5
SYNC: R13.2 U1.3 | length 220.2
  Top Layer w8: R13.2@399.94,785 397.48,787.46 432.54,787.46 457.41,762.59 457.41,709.24 475,691.65 475,660 490.47,644.53 U1.3
VCC: C4.1 D2.2 D3.2 R7.2 R14.2 U1.20 | length 1129.6
  Top Layer w8: v1(320,835) R7.2 ; U1.20 714.53,644.53 724.68,654.68 C4.1 v1(750,655) 750,688.35 D2.2 ; R14.2 v1(735,455) 755,455 773.35,473.35 D3.2
  Signal Layer 2 w8: v1(320,835) 330,845 435,845 438.13,841.87 733.13,841.87 750,825 v1(750,655) 750,630 763.78,616.22 763.78,498.78 735,470 v1(735,455)
VIN: Cin1.1 Cin2.1 Cin3.1 Cin4.1 J1.1 L3.1 Q2.5 Q2.6 Q2.7 Q2.8 Q2.9 R3.1 R4.2 U2.4 U2.5 | length 523.7
  Top Layer w8: v1(470,820) R3.1@499.68,820
  Signal Layer 2 w8: v1(470,820) v1(580,820)
  Bottom Layer w8: v3(245,1070) 314.69,1070 344.69,1040 344.69,945.31 v1(470,820)
  other v2: 1165.47,1100.59 1225.47,1100.59 1280.47,1100.59 1165.47,1160.59 1225.47,1160.59 1280.47,1160.59 1165.47,1220.59 1225.47,1220.59 1280.47,1220.59
  other v3: 810,1015 905,1015 1000,1015
VIN_IC: C2.1 R2.1 U1.27 | length 297.6
  Top Layer w8: v1(540,780.32) 540,735 550.47,724.53 U1.27
  Bottom Layer w8: v1(540,780.32) 540,825 561.81,846.81 657.13,846.81 665.32,855 v1(665.32,895)
VINSNS: C11.2 R3.2 U1.28 | length 367.6
  Top Layer w8: v1(500,780.31) 500,716.38 506.89,709.49 U1.28
  Bottom Layer w8: v1(500,780.31) 500,820 542.68,862.68 622.68,862.68 643.44,883.44 643.44,910.19 665.31,932.06 v1(665.31,935)
VOSNS: C1.1 R1.1 U1.9 | length 113.6
  Top Layer w8: C1.1@473.19,457.14 518.19,457.14 518.19,488.19 530,500 530,519.72 U1.9
VOUT: Co1.1 Co2.1 Co3.1 J2.1 Q1.5 Q1.6 Q1.7 Q1.8 Q1.9 R1.2 R8.1 | length 816.2
  Top Layer w8: R8.1 310,275 335,250 595,250 618.79,273.79 618.79,300 ; R1.2 520,325 545,300 618.79,300 ; v3(680,300) 618.79,300
  other v2: 1170.47,170.59 1225.47,170.59 1285.47,170.59 1170.47,230.59 1225.47,230.59 1285.47,230.59 1170.47,290.59 1225.47,290.59 1285.47,290.59
  other v3: 820,300 950,300
VRS: NT1.1 Q3.1 Q3.2 Q3.3 Q4.1 Q4.2 Q4.3 RS1.2 | length 46.1
  Top Layer w8: RS1.2@987.13,687.87 v3(995,680)
  Signal Layer 2 w8: NT1.1 v3(995,680)

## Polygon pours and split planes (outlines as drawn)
VRS on Top Layer "VRS" (solid, remove dead copper, pour order 8): 1175,998.28 1063.28,998.28 1050,985 1055,980 1055,850 950,850 950,500 1175,500 1175,998.28
HDRV1_N on Top Layer "HDRV1_N" (solid, remove dead copper, pour order 10): 1330,1210 1330,1000 1185,1000 1185,710 2000,710 2000,1210 1330,1210
GND on Top Layer "GND" (solid, remove dead copper, pour order 48): 0,1400 0,0 5,5 2100,5 2100,1400 0,1400
VIN on Top Layer "Vin" (solid, remove dead copper, pour order 2): 0,1395 0,1045 675.87,1045 675.87,1129.13 675,1130 765,1130 765,990 770,995 1050,995 1050,1015 1330,1015 1330,1400 0,1400
VOUT on Top Layer "Vout" (solid, remove dead copper, pour order 20): 650,355 650,0 1330,0 1330,355 650,355
HDRV2_N on Top Layer "HDRV2_N" (solid, remove dead copper, pour order 18): 1180,690 1180,370 1335,370 1335,0 2000,0 2000,690
HDRV1_N on Signal Layer 2 "HDRV1_N" (solid, remove dead copper, pour order 32): 1330,1210 1330,1000 1185,1000 1185,710 2000,710 2000,1210 1330,1210
GND on Signal Layer 2 "GND" (solid, remove dead copper, pour order 52): 0,1400 0,0 2100,0 2100,1400 0,1400
VIN on Signal Layer 2 "Vin" (solid, remove dead copper, pour order 24): 0,1400 0,1050 675.87,1050 675.87,1134.13 675,1135 765,1135 765,995 770,1000 1050,1000 1050,1020 1330,1020 1330,1405 0,1405
VOUT on Signal Layer 2 "Vout" (solid, remove dead copper, pour order 28): 650,355 650,0 1330,0 1330,355 650,355
HDRV2_N on Signal Layer 2 "HDRV2_N" (solid, remove dead copper, pour order 36): 1180,690 1180,370 1335,370 1335,0 2000,0 2000,690
HDRV1_N on Bottom Layer "HDRV1_N" (solid, remove dead copper, pour order 42): 1330,1210 1330,1000 1185,1000 1185,710 2000,710 2000,1210 1330,1210
GND on Bottom Layer "GND" (solid, remove dead copper, pour order 54): 0,1400 0,0 2100,0 2100,1400 0,1400
VIN on Bottom Layer "Vin" (solid, remove dead copper, pour order 40): 0,1400 0,1050 675.87,1050 675.87,1134.13 675,1135 765,1135 765,995 770,1000 1050,1000 1050,1020 1330,1020 1330,1405 0,1405
VOUT on Bottom Layer "Vout" (solid, remove dead copper, pour order 46): 650,355 650,0 1330,0 1330,355 650,355
HDRV2_N on Bottom Layer "HDRV2_N" (solid, remove dead copper, pour order 44): 1180,690 1180,370 1335,370 1335,0 2000,0 2000,690
GND on Signal Layer 1 "GND" (solid, remove dead copper, pour order 50): 0,1400 0,0 2100,0 2100,1400 0,1400

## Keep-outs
Keep-Out Layer:
  text ".Layer_Name" at 577,-858.49 h60

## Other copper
Top Layer:
  rectangle net GND: 700,599.57 763.78,625
  rectangle net GND: 645,620 815,630
  rectangle net GND: 761.81,614.33 795.06,621.22
  rectangle net GND: 690,610.57 715,625
  rectangle net GND: 550,513.62 570,550
  text ".Layer_Name" at 577,-858.49 h60
Bottom Layer:
  text ".Layer_Name" at 577,-858.49 h60

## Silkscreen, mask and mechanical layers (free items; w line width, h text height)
Top Overlay:
  lines w10: 275,95 275,135 275,1265 275,1280 290,1295 1975,1295 1985,1285 1985,95 1975,85 285,85 275,95
  text "'.PRJ_Number'.PCB_Rev-" at 955,1320 h72.27
  text "LM5175 80W Buck Boost" at 1350,1320 h72.83
  text "Solution Size: 43mm X 30mm" at -100,1290 h72.83
  text ".Layer_Name" at 577,-858.49 h60
Bottom Overlay:
  text ".Layer_Name" at 577,-858.49 h60
Top Paste:
  text ".Layer_Name" at 577,-858.49 h60
Bottom Paste:
  text ".Layer_Name" at 577,-858.49 h60
Top Solder:
  text ".Layer_Name" at 577,-858.49 h60
  text ".Layer_Name" at 577,-858.49 h60
Bottom Solder:
  text ".Layer_Name" at 577,-858.49 h60
Drill Guide:
  text ".Layer_Name" at 577,-858.49 h60
M1 Board Outline:
  the board outline again, w10
  text ".Layer_Name" at 577,-858.49 h60
M2 Board Dimensions:
  rectangle: 125,-400 500,-275
  rectangle: 0,-275 125,-150
  lines w7: 0,-275 1000,-275 ; 125,-400 125,-150 ; 250,-400 250,-150 ; 500,-400 500,-150 ; 750,-400 750,-150 ; 0,-400 0,-150 1000,-150 1000,-400 0,-400
  text ".Layer_Name" at 577,-858.49 h60
M3 3D STEP Top:
  text ".Layer_Name" at 577,-858.49 h60
M4 3D STEP Bottom:
  text ".Layer_Name" at 577,-858.49 h60
M5 Assembly Top:
  lines w10: -292,-930.17 6308,-930.17 ; -292,-726.83 6310,-726.83 ; -292,-523.5 -292,-1133.5 3713,-1133.5 6310,-1133.5 6310,-523.5 -291.5,-523.5 -291.5,-1133.5 1284,-1133.5 ; 2173,-1133.5 2173,-523.5 ; 3440,-726.83 3440,-523.5 ; 4280,-726.83 4280,-523.5 ; 4902,-1140 4902,-937.17
  text "COMPONENTS MARKED 'DNP' SHOULD NOT BE POPULATED." at 1153.5,-318.5 h60
  text "ASSEMBLY VARIANT:" at 1153,-434 h60
  text ".VariantName" at 2189,-434 h60
  text "PCB VIEWED FROM TOP SIDE" at -228.5,-655.67 h60
  text "BOARD #:" at 2248,-655.67 h60
  text ".PRJ_Number" at 2793.5,-655.67 h60
  text "REV:" at 3638,-655.67 h60
  text ".PCB_Rev" at 3929.5,-655.67 h60
  text "SVN REV:" at 4476,-655.67 h60
  text ".VersionControl_RevNumber" at 4982,-655.67 h60
  text "TID #:" at 2248,-859 h60
  text ".TID" at 2793.5,-859 h60
  text "PLOT NAME =" at -228.5,-1064.34 h60
  text ".plot_File_Name" at 577,-1064.34 h60
  text "GENERATED    :" at 2250,-1064.34 h60
  text ".Print_Date" at 3119.5,-1064.34 h60
  text ".Print_Time" at 3848.5,-1064.34 h60
  text "TEXAS INSTRUMENTS" at 5113,-1064.34 h60
M6 Assembly Bottom:
  lines w10: -292.5,-727.33 6309.5,-727.33 ; -290.5,-930.67 6309.5,-930.67 ; 1115.5,-1140.5 1115.5,-937.67 ; 1737.5,-727.33 1737.5,-524 ; 2577.5,-727.33 2577.5,-524 ; 3844.5,-1134 3844.5,-524 ; 4733.5,-1134 6309,-1134 6309,-524 -292.5,-524 -292.5,-1134 2304.5,-1134 6309.5,-1134 6309.5,-524
  text "COMPONENTS MARKED 'DNP' SHOULD NOT BE POPULATED." at 6102,-318 h60
  text ".VariantName" at 5058,-434 h60
  text "ASSEMBLY VARIANT:" at 6097,-434 h60
  text ".VersionControl_RevNumber" at 1035.5,-656.17 h60
  text "SVN REV:" at 1541.5,-656.17 h60
  text ".PCB_Rev" at 2088,-656.17 h60
  text "REV:" at 2379.5,-656.17 h60
  text ".PRJ_Number" at 3224,-656.17 h60
  text "BOARD #:" at 3769.5,-656.17 h60
  text "PCB VIEWED FROM BOTTOM SIDE" at 6246,-656.17 h60
  text ".TID" at 3224,-859.5 h60
  text "TID #:" at 3769.5,-859.5 h60
  text "TEXAS INSTRUMENTS" at 904.5,-1064.84 h60
  text ".Print_Time" at 2169,-1064.84 h60
  text ".Print_Date" at 2898,-1064.84 h60
  text "GENERATED    :" at 3767.5,-1064.84 h60
  text ".plot_File_Name" at 5440.5,-1064.84 h60
  text "PLOT NAME =" at 6246,-1064.84 h60
M8 LPKF Text Bottom:
  drawing of 425 lines, arcs and shapes, not listed
  text "Layer" at 6132.5,7715.03 h60
  text "Name" at 6542.41,7715.03 h60
  text "Material" at 7482.16,7715.03 h60
  text "Thickness" at 8341.92,7715.03 h60
  text "Constant" at 8991.76,7715.03 h60
  text "Board Layer Stack" at 9561.62,7715.03 h60
  text "1" at 6132.5,7595.03 h60
  text "Top Overlay" at 6542.41,7595.03 h60
  text "2" at 6132.5,7475.03 h60
  text "Top Solder" at 6542.41,7475.03 h60
  text "Solder Resist" at 7482.16,7475.03 h60
  text "0.40mil" at 8341.92,7475.03 h60
  text "3.5" at 8991.76,7475.03 h60
  text "3" at 6132.5,7355.03 h60
  text "Top Layer" at 6542.41,7355.03 h60
  text "Copper" at 7482.16,7355.03 h60
  text "2.80mil" at 8341.92,7355.03 h60
  text "4" at 6132.5,7235.03 h60
  text "Dielectric1" at 6542.41,7235.03 h60
  text "FR-4" at 7482.16,7235.03 h60
  text "20.00mil" at 8341.92,7235.03 h60
  text "4.8" at 8991.76,7235.03 h60
  text "5" at 6132.5,7115.03 h60
  text "Signal Layer 1" at 6542.41,7115.03 h60
  text "Copper" at 7482.16,7115.03 h60
  text "2.80mil" at 8341.92,7115.03 h60
  text "6" at 6132.5,6995.03 h60
  text "Dielectric 3" at 6542.41,6995.03 h60
  text "17.00mil" at 8341.92,6995.03 h60
  text "4.2" at 8991.76,6995.03 h60
  text "7" at 6132.5,6875.03 h60
  text "Signal Layer 2" at 6542.41,6875.03 h60
  text "Copper" at 7482.16,6875.03 h60
  text "2.80mil" at 8341.92,6875.03 h60
  text "8" at 6132.5,6755.03 h60
  text "Dielectric 2" at 6542.41,6755.03 h60
  text "20.00mil" at 8341.92,6755.03 h60
  text "4.2" at 8991.76,6755.03 h60
  text "9" at 6132.5,6635.03 h60
  text "Bottom Layer" at 6542.41,6635.03 h60
  text "Copper" at 7482.16,6635.03 h60
  text "2.80mil" at 8341.92,6635.03 h60
  text "10" at 6132.5,6515.03 h60
  text "Bottom Solder" at 6542.41,6515.03 h60
  text "Solder Resist" at 7482.16,6515.03 h60
  text "0.40mil" at 8341.92,6515.03 h60
  text "3.5" at 8991.76,6515.03 h60
  text "11" at 6132.5,6395.03 h60
  text "Bottom Overlay" at 6542.41,6395.03 h60
M9 Title Sheet:
  drawing of 57 lines, arcs and shapes, not listed
  text "1" at 739.84,8036.5 h70
  text "2" at 3235.5,8036.5 h70
  text "3" at 5724.84,8036.5 h70
  text "4" at 8231.51,8036.5 h70
  text "5" at 10730.5,8036.5 h70
  text "6" at 13235.5,8036.5 h70
  text "A" at -416.5,6893.5 h70
  text "A" at 14383.5,6893.5 h70
  text "B" at -416.5,4513.5 h70
  text "B" at 14383.5,4513.5 h70
  text "C" at -416.5,2138.5 h70
  text "C" at 14383.5,2138.5 h70
  text "PROJECT TITLE:" at 11343.5,277.5 h45
  text ".PRJ_Title" at 11393.5,144.17 h70
  text "DESIGNED FOR:" at 11343.5,-23.5 h45
  text ".PRJ_Customer" at 11393.5,-163.5 h70
  text "D" at -416.5,-231.5 h70
  text "D" at 14383.5,-231.5 h70
  text "FILE NAME:" at 11343.5,-323.5 h45
  text ".PCB_File_Name_No_Path" at 11393.5,-443.5 h70
  text "Texas Instruments (TI) and/or its licensors do not warrant the accuracy or completeness of this specification" at 6374,-605.34 h45
  text "ENGINEER:" at 11343.5,-613.5 h45
  text "LAYOUT BY:" at 12848.5,-613.5 h45
  text "or any information contained therein. TI and/or its licensors do not warrant that this design will meet" at 6329.01,-718 h45
  text ".PRJ_Engineer" at 11393.5,-768.49 h70
  text ".PCB_Layout" at 12899,-768.49 h70
  text "the specifications, will be suitable for your application or fit for any particular purpose, or will operate in" at 6329.01,-830.67 h45
  text ".Layer_Name" at 577,-858.49 h60
  text "ALTIUM DESIGNER VERSION:" at 12848.5,-923.5 h45
  text "an implementation. TI and/or its licensors do not warrant that the design is production worthy. You should" at 6329.01,-943.33 h45
  text "completely validate and test your design implementation to confirm the system functionality for your application." at 6374,-1056 h45
  text ".print_Scale" at 11393.5,-1056.83 h70
  text ".Application_BuildNumber" at 12899,-1056.83 h70
  text "1" at 739.84,-1263.5 h70
  text "2" at 3235.5,-1263.5 h70
  text "3" at 5724.84,-1263.5 h70
  text "4" at 8231.51,-1263.5 h70
  text "5" at 10730.5,-1263.5 h70
  text "6" at 13235.5,-1263.5 h70
M10 Fab Notes:
  drawing of 173 lines, arcs and shapes, not listed
  text "DESIGN INFORMATION" at 12378.02,6201 h60
  text "MIN. TRACK WIDTH:" at 11733.46,6021 h60
  text "8" at 12829.7,6021 h60
  text "MIL" at 12984.46,6021 h60
  text "MIN. CLEARANCE:" at 11733.46,5889 h60
  text "0.2" at 12769.7,5889 h60
  text "mm" at 12984.46,5889 h60
  text "MIN. VIA PAD SIZE:" at 11733.46,5757 h60
  text "MIL" at 12984.46,5757 h60
  text "20" at 12791.71,5749 h60
  text "0.127mm (5MIL)" at 12428.46,5615.29 h60
  text "MINIMUM ANNULAR RING" at 11404.23,5611 h60
  text "EXTERNAL" at 13136.46,5611 h60
  text "PER" at 11604.23,5493 h60
  text "IPC-D-275 CLASS 2 LEVEL C" at 11824.23,5493 h60
  text "MIL, HOLES" at 13312.46,5380.71 h60
  text "+/-" at 12920,5380 h60
  text "+/-" at 13774,5380 h60
  text "REGISTRATION TOLERANCES:" at 11404.23,5375 h60
  text "METAL" at 12604,5375 h60
  text "5" at 13180.2,5375 h60
  text "3" at 14013.2,5375 h60
  text "MIL" at 14129.46,5375 h60
  text "+/-" at 13774,5262 h60
  text "HOLE SIZE TOLERANCE (UNLESS OTHERWISE SPECIFIED):" at 11404.23,5257 h60
  text "3" at 14013.2,5257 h60
  text "MIL" at 14129.46,5257 h60
  text "MATERIAL:" at 11329.46,5047.54 h60
  text "FR-4 High Tg" at 12315.9,4907.21 h60
  text "FR-408" at 11750.46,4898.64 h60
  text "OTHER" at 13238.46,4898.64 h60
  text "X" at 12161,4895 h60
  text "62 MIL (1.6mm) +/-10%" at 12070.56,4735.92 h60
  text "THICKNESS:" at 11404.23,4731.64 h60
  text "X" at 11942.4,4731.64 h60
  text "OTHER" at 13355.46,4731.64 h60
  text "TOLERANCE:" at 11404.23,4573.64 h60
  text "X" at 12243.53,4573.64 h60
  text "ANSI IPC-6012 TYPE 3 CLASS 2" at 12430.48,4573.64 h60
  text "OTHER +/-" at 12430.46,4417.64 h60
  text "BOW & TWIST:" at 11404.23,4260.64 h60
  text "X" at 12243.53,4260.64 h60
  text "ANSI IPC-6012 TYPE 3 CLASS 2" at 12430.48,4260.64 h60
  text "OTHER +/-" at 12430.46,4102.13 h60
  text "DRILLING:" at 11329.46,3963.64 h60
  text "REFERENCE:" at 11404.23,3846.64 h60
  text "X" at 12052.46,3846.64 h60
  text "AS SHOWN" at 12239.46,3846.64 h60
  text "X" at 12953.46,3846.64 h60
  text "NC_DRILL FILES" at 13090.46,3846.64 h60
  text "PTH COPPER THICKNESS:" at 11404.23,3688.64 h60
  text "X" at 12534.46,3688.64 h60
  text "20-30 um" at 12671.46,3688.64 h60
  text "OTHER" at 13388.46,3688.64 h60
  text "BOARD FINISH:" at 11329.46,3529.64 h60
  text "SILKSCREEN:" at 11484.68,3411.64 h60
  text "X" at 12433.46,3411.64 h60
  text "TOP" at 12559.46,3411.64 h60
  text "X" at 12943.46,3411.64 h60
  text "BOTTOM" at 13070.46,3411.64 h60
  text "SILKSCREEN COLOR:" at 11484.68,3244.64 h60
  text "X" at 12432.42,3244.64 h60
  text "WHITE" at 12559.46,3244.64 h60
  text "OTHER" at 13070.46,3244.64 h60
  text "X" at 12563.42,3085.44 h60
  text "GREEN" at 12690.46,3085.44 h60
  text "OTHER" at 13308.46,3085.44 h60
  text "SOLDER RESIST COLOR:" at 11484.68,3074.64 h60
  text "X" at 12563.42,2915.44 h60
  text "MATTE" at 12690.46,2915.44 h60
  text "SEMI-GLOSS" at 13308,2914.8 h60
  text "IMMERSION GOLD (ENIG)" at 12390.46,2726.92 h60
  text "ENEPIG" at 13728,2723.64 h60
  text "SURFACE FINISH:" at 11329.46,2722.64 h60
  text "X" at 12203.51,2722.64 h60
  text "IMM. TIN/SILVER OR EQUIV" at 11659,2565.64 h60
  text "OTHER" at 13090.46,2565.64 h60
  text "ARRAY/PANEL:" at 11329.46,2386.64 h60
  text "CUT AND TRIM PER M1 BOARD OUTLINE" at 12390.46,2382.35 h60
  text "X" at 12200,2380 h60
  text "N.C. ROUTE" at 12390.46,2230.64 h60
  text "V. SCORE" at 13256.46,2230.64 h60
  text "CERTIFICATION:" at 11329.46,2093.64 h60
  text "MATERIALS AND WORKMANSHIP FOR ALL PCBS" at 12054.46,2093.64 h60
  text "TO MEET OR EXCEED THE REQUIREMENTS OF:" at 12054.46,1995.64 h60
  text "X" at 11680.96,1859.13 h60
  text "ANSI IPC-A-600F CLASS ->" at 11819.96,1859.13 h60
  text "X" at 13459.02,1859.13 h60
  text "2" at 13577.96,1859.14 h60
  text "1" at 13262.96,1857.64 h60
  text "3" at 13931.96,1857.64 h60
  text "X" at 12495.02,1699.64 h60
  text "RoHS" at 12631.96,1699.64 h60
  text "OTHER" at 13276.36,1699.64 h60
  text "PER ORDER" at 13673.42,1699.64 h60
  text "ALL BOARDS MUST MEET OR EXCEED UL94-V0 REQUIREMENTS." at 11357,1534 h60
  text "PCB MUST BEAR THE UL94V-0 UL REGISTERED MATERIAL ID NUMBER" at 11357,1414 h60
  text "ADDITIONAL REQUIREMENTS:" at 11329.46,1240.64 h60
  text "MICROSECTION:" at 11404.23,1125.64 h60
  text "YES" at 12309.96,1125.64 h60
  text "X" at 13050,970 h60
  text "REQUIRED" at 13171.46,969.49 h60
  text "BARE BOARD ELEC. TEST:" at 11404.23,966.64 h60
  text "NONE" at 12709.96,966.64 h60
  text "PER ORDER" at 13763.46,966.64 h60
  text ".Layer_Name" at 577,-858.49 h60
M11 Gerber Information:
  lines w10: -292,-930.17 6308,-930.17 ; -292,-726.83 6310,-726.83 ; -292,-523.5 -292,-1133.5 3713,-1133.5 6310,-1133.5 6310,-523.5 -291.5,-523.5 -291.5,-1133.5 1284,-1133.5 ; 2173,-1133.5 2173,-523.5 ; 3440,-726.83 3440,-523.5 ; 4280,-726.83 4280,-523.5 ; 4902,-1140 4902,-937.17
  text "ALL ARTWORK VIEWED FROM TOP SIDE" at -228.5,-655.67 h60
  text "BOARD #:" at 2248,-655.67 h60
  text ".PRJ_Number" at 2793.5,-655.67 h60
  text "REV:" at 3638,-655.67 h60
  text ".PCB_Rev" at 3929.5,-655.67 h60
  text "SVN REV:" at 4476,-655.67 h60
  text ".VersionControl_RevNumber" at 4982,-655.67 h60
  text "LAYER NAME =" at -228.5,-858.49 h60
  text "TID #:" at 2248,-859 h60
  text ".TID" at 2793.5,-859 h60
  text "PLOT NAME =" at -228.5,-1064.34 h60
  text ".plot_File_Name" at 577,-1064.34 h60
  text "GENERATED    :" at 2250,-1064.34 h60
  text ".Print_Date" at 3119.5,-1064.34 h60
  text ".Print_Time" at 3848.5,-1064.34 h60
  text "TEXAS INSTRUMENTS" at 5113,-1064.34 h60
M12 Stackup:
  text ".Layer_Name" at 577,-858.49 h60
M13 Component Bodies Top:
  text ".Layer_Name" at 577,-858.49 h60
M14 Component Bodies Bottom:
  text ".Layer_Name" at 577,-858.49 h60
M15 Courtyards Top:
  text ".Layer_Name" at 577,-858.49 h60
M16 Courtyards Bottom:
  text ".Layer_Name" at 577,-858.49 h60
Drill Drawing:
  lines w10: 4736.14,2201.9 4791.46,2201.9 4763.8,2146.59 4736.14,2201.9 ; 4736.14,2271.04 4791.46,2271.04 4791.46,2326.36 4736.14,2326.36 4736.14,2271.04 ; 4736.14,2409.33 4749.97,2409.33 4749.97,2395.5 4777.63,2395.5 4777.63,2409.33 4791.46,2409.33 4791.46,2436.99 4777.63,2436.99 4777.63,2450.82 4749.97,2450.82 4749.97,2436.99 4736.14,2436.99 4736.14,2409.33 ; 4736.14,2519.96 4763.8,2533.79 4791.46,2519.96 4777.63,2547.62 4791.46,2575.28 4763.8,2561.45 4736.14,2575.28 4749.97,2547.62 4736.14,2519.96 ; 4736.14,2658.25 4749.97,2658.25 4763.8,2644.42 4777.63,2658.25 4791.46,2658.25 4777.63,2672.08 4791.46,2685.91 4777.63,2685.91 4763.8,2699.74 4749.97,2685.91 4736.14,2685.91 4749.97,2672.08 4736.14,2658.25
  lines w12: 4686,2109.25 7918.76,2109.25 ; 4686,2731.54 7918.76,2731.54 ; 5024.17,1984.79 5024.17,2856 ; 5356.28,1984.79 5356.28,2856 ; 5993.29,1984.79 5993.29,2856 ; 6252.64,1984.79 6252.64,2856 ; 6628.06,1984.79 6628.06,2856 ; 7351.91,1984.79 7351.91,2856 ; 4686,1984.79 7918.76,1984.79 7918.76,2856 4686,2856 4686,1984.79
  text "Symbol" at 4760.68,2768.88 h72
  text "Quantity" at 5061.51,2768.88 h72
  text "Finished Hole Size" at 5393.62,2768.88 h72
  text "Plated" at 6030.62,2768.88 h72
  text "Hole Type" at 6289.98,2768.88 h72
  text "Drill Layer Pair" at 6665.4,2768.88 h72
  text "Hole Tolerance" at 7389.25,2768.88 h72
  text "41" at 5061.51,2644.42 h60
  text "10.00mil (0.254mm)" at 5393.62,2644.42 h60
  text "PTH" at 6030.62,2644.42 h60
  text "Round" at 6289.98,2644.42 h60
  text "Top Layer - Bottom Layer" at 6665.4,2644.42 h60
  text "19" at 5061.51,2519.96 h60
  text "15.00mil (0.381mm)" at 5393.62,2519.96 h60
  text "PTH" at 6030.62,2519.96 h60
  text "Round" at 6289.98,2519.96 h60
  text "Top Layer - Bottom Layer" at 6665.4,2519.96 h60
  text "40" at 5061.51,2395.5 h60
  text "25.00mil (0.635mm)" at 5393.62,2395.5 h60
  text "PTH" at 6030.62,2395.5 h60
  text "Round" at 6289.98,2395.5 h60
  text "Top Layer - Bottom Layer" at 6665.4,2395.5 h60
  text "2" at 5061.51,2271.04 h60
  text "40.00mil (1.016mm)" at 5393.62,2271.04 h60
  text "PTH" at 6030.62,2271.04 h60
  text "Round" at 6289.98,2271.04 h60
  text "Top Layer - Bottom Layer" at 6665.4,2271.04 h60
  text "4" at 5061.51,2146.59 h60
  text "98.43mil (2.500mm)" at 5393.62,2146.59 h60
  text "PTH" at 6030.62,2146.59 h60
  text "Round" at 6289.98,2146.59 h60
  text "Top Layer - Bottom Layer" at 6665.4,2146.59 h60
  text "106 Total" at 5061.51,2022.13 h60
  text ".Layer_Name" at 577,-858.49 h60
M17 Embedded Cavity:
  text ".Layer_Name" at 577,-858.49 h60
M18 Embedded Assembly:
  text ".Layer_Name" at 577,-858.49 h60
M19 Embedded Keepout:
  text ".Layer_Name" at 577,-858.49 h60

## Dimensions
0,0 to 2100,0 on M2 Board Dimensions
0,0 to 0,1400 on M2 Board Dimensions
0,-400 to 1000,-400 on M2 Board Dimensions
